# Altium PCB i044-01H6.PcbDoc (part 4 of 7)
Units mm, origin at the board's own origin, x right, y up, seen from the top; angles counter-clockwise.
Board outline 42 x 29.01 mm, 8 copper layers (Top Layer, Mid-Layer 1, Mid-Layer 2, Mid-Layer 3, Mid-Layer 4, Mid-Layer 5, Mid-Layer 6, Bottom Layer), stack 1.474 mm thick; 235 components, 197 nets, 1006 pads, 1183 vias.
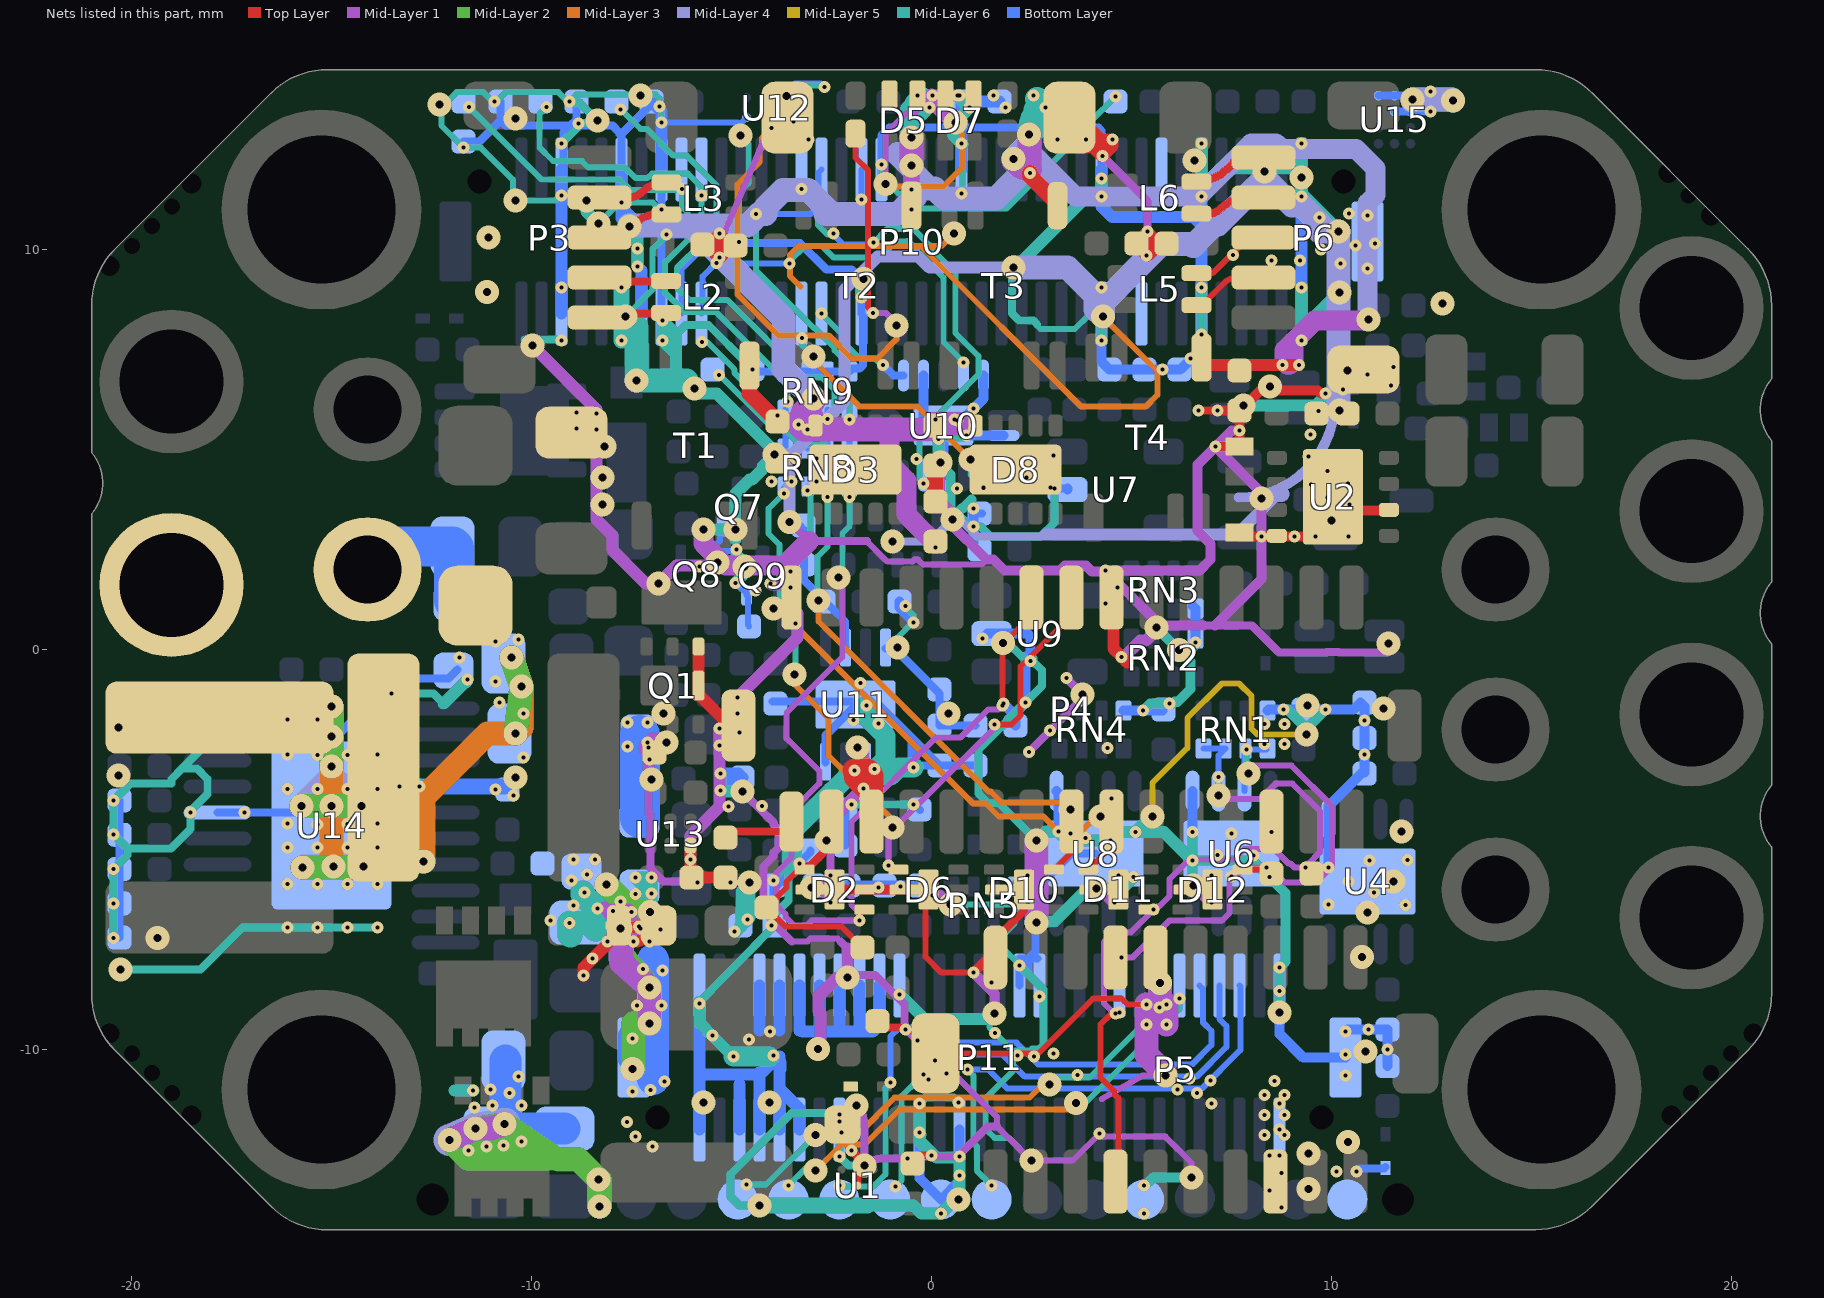
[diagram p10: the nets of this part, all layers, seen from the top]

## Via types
v1: diameter 0.3/0.3 (per signal layer), hole 0.1, Mid-Layer 6 to Bottom Layer, 515 vias
v2: diameter 0.3/0.3 (per signal layer), hole 0.1, Top Layer to Mid-Layer 1, 392 vias
v3: diameter 0.6, hole 0.2, Mid-Layer 1 to Mid-Layer 6, 276 vias

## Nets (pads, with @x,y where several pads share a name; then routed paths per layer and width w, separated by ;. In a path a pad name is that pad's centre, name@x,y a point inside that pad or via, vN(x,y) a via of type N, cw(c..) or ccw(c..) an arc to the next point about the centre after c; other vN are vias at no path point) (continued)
ENC_Z_IN/CLK_OUT_N: D12.6 P5.8 R11.2 RN1.1 RN1.3 U6.7 | length 14.7
  Top Layer w0.15: D12.6@7.775,-5.5 8.4,-5.5 R11.2@8.5,-5.6
  Top Layer w0.25: P5.8@4.6,-7.22 P5.8@4.6,-7.7 v2(4.75,-7.7)
  Mid-Layer 1 w0.15: v2(4.75,-7.7) 5.019,-7.7 5.944,-6.775 7.261,-6.775 7.45,-6.586 7.45,-5.814 7.814,-5.45 v2(8.375,-5.45) 8.452,-5.45 8.827,-5.825 9.505,-5.825 9.521,-5.81 9.627,-5.81 10.007,-5.429 10.007,-3.907 9,-2.9 7.975,-2.9 7.925,-2.95 v3(7.925,-3.094)
  Mid-Layer 6 w0.15: v3@7.875,-3.044 v1(7.875,-2.5)
  Bottom Layer w0.15: U6.7@7.825,-3.538 7.825,-2.5 v1(7.875,-2.5) RN1.1@8.375,-2.5
ENC_Z_IN/CLK_OUT_P: D11.4 P5.7 R11.1 RN1.5 RN1.7 U6.6 | length 19.6
  Top Layer w0.15: P5.7@4.575,-13.275 P5.7@4.6,-13.3 4.675,-13.225 4.675,-11.219 4.67,-11.213 4.58,-11.124 4.58,-11.052 4.232,-10.704 4.226,-10.699 4.225,-10.698 4.227,-10.332 4.225,-10.323 4.225,-9.369 4.494,-9.1 v2(4.6,-9.1)
  Mid-Layer 1 w0.15: v2(4.6,-9.1) 4.575,-9.1 4.309,-8.834 4.309,-7.316 4.55,-7.075 4.975,-7.075 v2(5.55,-6.5) 5.625,-6.425 5.686,-6.425 5.95,-6.161 5.95,-6.091 5.95,-5.736 6.436,-5.25 7.555,-5.25 7.823,-4.981 8.541,-4.981 8.559,-5 8.576,-5 8.926,-5.35 8.976,-5.35 9.076,-5.45 v2(9.35,-5.45) 9.4,-5.45 9.4,-5.35 9.424,-5.35 9.707,-5.067 9.707,-4.031 9.026,-3.35 8.604,-3.35 8.218,-3.736 7.411,-3.736 7.325,-3.65 v3(7.175,-3.65)
  Mid-Layer 6 w0.15: v3@7.175,-3.444 7.18,-3.439 v1(7.18,-3.18)
  Bottom Layer w0.15: RN1.7@6.8,-2.475 RN1.5@7.35,-2.475 7.175,-2.65 7.18,-2.655 v1(7.18,-3.18) 7.18,-3.532 U6.6@7.175,-3.538
ETH0_LED_LINK: D4.1 U12.B2 | length 18.4
  Top Layer w0.15: D4.1@-1.9,12.9 -1.9,12.3 -1.594,11.994 -1.594,8.554 v2(-1.46,8.42)
  Mid-Layer 1 w0.15: v2(-1.46,8.42) -1.145,8.42 v3@-0.825,8.1
  Mid-Layer 3 w0.15: v3(-3.627,13.837) -3.627,13.403 -4.235,12.795 -4.235,12.545 -4.3,12.48 -4.3,12.185 -4.85,11.635 -4.85,8.878 -3.827,7.855 -2.573,7.855 -1.993,7.275 -1.358,7.275 -0.877,7.756 v3(-0.877,8.1)
  Mid-Layer 6 w0.15: v3(-3.627,13.837) -3.627,13.948 -3.475,14.1 -2.71,14.1 v1(-2.67,14.06)
  Bottom Layer w0.15: U12.B2@-3.625,13.8 -3.625,13.93 -3.418,14.15 -2.76,14.15 v1(-2.67,14.06)
ETH0_RX_N: L3.1 P3.4 | length 1.8
  Top Layer w0.2: P3.4@-8.3,11.3 -7.591,11.3 ccw(c-7.591,11.821) -7.222,11.453 cw(c-6.625,10.855) L3.1@-6.625,11.7
ETH0_RX_P: L3.2 P3.3 | length 1.8
  Top Layer w0.2: P3.3@-8.235,10.3 ccw(c-8.235,11.41) -7.45,10.625 cw(c-6.786,9.961) -6.786,10.9 L3.2@-6.625,10.9
ETH0_TX_N: L2.1 P3.2 | length 1.7
  Top Layer w0.2: P3.2@-8.2,9.2 L2.1@-6.625,9.2
  Top Layer w0.25: P3.2@-8.3,9.3 P3.2@-8.2,9.2
ETH0_TX_P: L2.2 P3.1 | length 1.6
  Top Layer w0.2: P3.1@-8.2,8.4 L2.2@-6.625,8.4
ETH1_RX_N: L5.1 P6.4 | length 1.9
  Top Layer w0.15: L5.1@6.625,8.61 ccw(c6.625,8.936) 6.855,8.705 7.316,9.166 cw(c7.64,8.841) 7.64,9.3 P6.4@8.3,9.3
ETH1_RX_P: L5.2 P6.3 | length 2
  Top Layer w0.15: L5.2@6.625,9.41 7.029,9.41 7.919,10.3 P6.3@8.3,10.3
ETH1_TX_N: L6.1 P6.2 | length 1.8
  Top Layer w0.2: L6.1@6.625,10.9 6.923,10.9 ccw(c6.923,11.327) 7.225,11.025 cw(c7.889,10.361) 7.889,11.3 P6.2@8.3,11.3
ETH1_TX_P: L6.2 P6.1 | length 1.9
  Top Layer w0.2: L6.2@6.625,11.7 ccw(c6.625,12.786) 7.393,12.018 7.675,12.3 P6.1@8.3,12.3
ETH_MOD_LED_G: P10.66
ETH_MOD_LED_R: P10.63
FAULT_SIGNAL: P10.36 R27.1 | length 8.4
  Mid-Layer 6 w0.15: v1(-1.75,11.25) -1.709,11.25 -1.484,11.025 1.87,11.025 3.57,12.725 3.647,12.725 3.995,13.073 3.995,13.22 v1(4.6,13.825)
  Bottom Layer w0.15: v1(-1.75,11.25) P10.36@-1.75,12
GND_A: C24.1 C25.1 C32.1 C33.2 C34.1 L8.1 P11.1 P11.2 P11.5 P11.7 P11.8 P11.9 P11.10 P11.11 P11.12 P11.14 P11.16 P11.18 P11.20 U11.0 U11.4 | length 47
  Mid-Layer 6 w0.2: v1@-5.8,-8.812 -3.999,-6.975 v1@-3.962,-6.937 ; v1(-4,-6.9) -4,-6.698 -3.577,-6.275 -3.577,-5.359 ; v1(-3.95,-5.775) -3.95,-5.732 -3.577,-5.359 ; -3.5,-5.282 -3.577,-5.359
  Mid-Layer 6 w0.3: v1@-5.8,-8.812 v1(-5.8,-8.85) -5.784,-9.344 v1(-5.478,-9.65) v1(-4.953,-10.175)
  Mid-Layer 6 w0.5: v1(-4.953,-10.175) v1@-4.05,-10.175 ; -3.5,-5.282 -3.5,-4.56 -2.487,-3.547 -2.475,-3.547 -2.101,-3.173 -2.101,-3.15 -1.56,-3.15 ; v1(-1.625,-1.4) -1.625,-1.685 -1.15,-2.16 -1.15,-2.74 -1.56,-3.15 ; v1(-0.45,-2.95) -0.825,-2.95 -1.025,-3.15 -1.56,-3.15
  Bottom Layer w0.2: v1(-4,-6.9) -3.95,-6.85 v1(-3.95,-5.775) -3.95,-5.925 L8.1@-3.925,-5.9 -3.864,-5.9 -3.025,-5.061 C33.2@-3.025,-5.025 ; C34.1@-3.975,-1.3 -2,-1.3 U11.0@-1.9,-1.4 ; U11.4@-2.65,-2.825 U11.4@-2.65,-2.8 -2.65,-2.15 U11.0@-1.9,-1.4 ; v1@-0.498,-2.864 -0.498,-2.314 ; -0.4,-2.35 -0.4,-2.9 C25.1@0.2,-2.9 ; C24.1@1.1,-2.9 C25.1@0.2,-2.9 ; U11.0@-1.9,-1.4 v1(-1.625,-1.4) -1.3,-1.4 C25.1@0.2,-2.9
  Bottom Layer w0.3: P11.1@-5.8,-12 -5.8,-10.6 ; v1(-5.8,-8.85) -5.8,-10.6 ; P11.5@-4.8,-12 -4.8,-10.875 ; P11.7@-4.3,-12 -4.3,-10.625 ; -4.3,-10.575 -4.3,-10.625 ; -4.3,-9.525 P11.8@-4.3,-8.4 ; P11.9@-3.8,-12 -3.8,-10.3 ; -3.8,-10.975 -3.3,-11.475 P11.11@-3.3,-12 ; -3.8,-10.175 -3.8,-10.3 ; -3.8,-9.525 P11.10@-3.8,-8.4 ; -3.775,-10.486 -3.775,-10.325 -3.8,-10.3 ; -3.3,-9.525 P11.12@-3.3,-8.4 ; -3.225,-9.55 -1.775,-9.55 ; -2.8,-9.525 P11.14@-2.8,-8.4 ; -2.3,-9.525 P11.16@-2.3,-8.4 ; P11.18@-1.8,-8.4 -1.8,-9.525 -1.775,-9.55 ; P11.20@-1.3,-8.4 -1.3,-9.377 -1.473,-9.55 -1.775,-9.55 ; -5.8,-10.6 -5.775,-10.625 -4.3,-10.625 ; -4.3,-10.625 -3.95,-10.275 v1(-3.95,-10.15) -3.8,-10.3
  other v1: -4.563,-9.75 -4.032,-9.55 -3.3,-5.35 -1.325,-1.847 -1.954,-1.763 -1.773,-0.833
GND_D: C5.2 C6.1 C7.2 C8.1 C9.1 C10.2 C12.2 C13.1 C14.1 C15.1 C16.2 C17.2 C18.2 C19.2 C20.2 C21.2 C22.2 C23.1 C26.2 C27.2 C28.2 C30.2 C35.1 C36.2 C37.2 C39.2 C43.2 C53.1 C56.1 D2.2 D2.5 D3.EP D5.3 D5.4 D6.2 D7.3 D7.4 D8.EP D10.2 D11.2 D12.2 D13.2 D14.2 D25.1 D26.1 L4.2 L8.2 L12.2 P4.6 P4.13 P4.26 P4.29 P4.S2 P5.2 P5.10 P5.15 P5.S1 P6.S2 P10.5 P10.6 P10.11 P10.12 P10.15 P10.16 P10.35 P10.38 P10.46 P10.59 P10.60 P10.69 P10.70 P10.79 P10.80 P10.S2 P11.15 P11.22 P11.23 P11.27 P11.34 P11.36 P11.44 P11.59 P11.60 P11.S2 pad.10 pad.14 pad.18 Q1.4 Q1.7 Q7.2 Q8.2 Q9.2 R3.1 R4.1 R7.1 R8.1 R20.2 R21.2 R23.2 R24.2 R29.2 R41.1 R48.2 R54.1 RN1.2 RN2.2 RN3.8 RN4.7 RN5.2 RN9.1 RN9.3 RN9.5 RN9.7 U1.A2 U1.B2 U2.2 U2.8 U2.9 U4.0 U4.5 U6.0 U6.5 U7.2 U8.0 U8.5 U9.2 U10.1 U10.4 U10.7 U10.10 U10.13 U10.EP U12.D1 U13.3 U15.C2 U15.C3 U15.D1 U15.D2 U15.D3 | length 482.6
  Top Layer w0.15: D6.2@-0.075,-6 -0.15,-6.075 -0.15,-7.68 0.245,-8.075 v2(1.05,-8.075) ; P5.S1@0.1,-10.1 v2@2.15,-10.1 ; v2(2.15,-10.15) v2@2.15,-10.1 ; v2(5.375,-8.871) 4.901,-8.871 4.755,-8.725 4.037,-8.725 2.662,-10.1 v2@2.15,-10.1
  Top Layer w0.2: v2@-1.977,-12.548 -1.85,-12.675 U1.A2@-1.85,-13 U1.B2@-1.85,-13.4 ; R54.1@-1.35,-9.29 -1.196,-9.444 -0.733,-9.444 -0.677,-9.5 -0.5,-9.5 P5.S1@0.1,-10.1 ; R48.2@-0.45,-12.85 -0.25,-12.65 v2(0,-12.65) ; P5.2@1.6,-7.7 1.6,-7.24 2.312,-6.527 D10.2@2.312,-6 ; v2(6.675,5.975) v2(7.15,5.975)
  Top Layer w0.25: D2.2@-2.425,-6 D2.5@-1.675,-6 D6.2@-0.625,-6 D6.2@-0.075,-6 ; v2(1.05,-8.075) 1.35,-7.775 1.525,-7.775 P5.2@1.6,-7.7 ; v2(7.1,5.075) D14.2@7.7,5.075 v2(7.7,5.475) C12.2@7.7,5.975 ; v2(7.15,5.975) C12.2@7.7,5.975 ; D13.2@7.7,2.825 v2(8.25,2.825) v2(9.075,2.825) U2.9@9.425,2.825 ; v2(9.85,6.4) 9.736,6.4 9.661,6.475 8.214,6.475 7.714,5.975 C12.2@7.7,5.975 ; U2.9@10.35,3.475 U2.2@11.425,3.475
  Top Layer w0.3: U13.3@-6.025,-4.9 v2(-6.025,-5.25) -6.025,-5.675 R41.1@-6,-5.7 L4.2@-5.15,-5.7 ; Q1.4@-5.825,0.075 Q1.7@-5.825,-0.9 -5.825,-1.12 -5.045,-1.9 P4.S2@-4.825,-1.9 ; P4.13@4.5,1.3 4.55,1.3 4.55,0.024 v2(4.755,-0.181) 4.9,-0.326
  Top Layer w0.4: C8.1@0.1,3.7 C9.1@0.1,4.6
  Top Layer w0.6: v2(-1.925,-3.025) -1.598,-3.025 v2@-1.531,-3.092 ; P4.26@-1.5,-4.3 P4.26@-1.5,-3.581 ; -1.5,-3.156 P4.26@-1.5,-3.548 ; P4.26@-1.5,-3.581 -1.89,-3.19 -1.857,-3.19 P4.26@-1.5,-3.548 ; P4.26@-1.5,-3.581 P4.26@-1.5,-3.548
  Mid-Layer 1 w0.15: -3.493,-7.297 -3.103,-7.297 -3.03,-7.225 -2.35,-7.225 -2.278,-7.297 ; -1.615,2.712 -1.103,2.2 -0.478,2.2 -0.425,2.253 -0.342,2.253 -0.214,2.125 1.244,2.125 1.372,2.253 ; v3(-1.15,11.64) -1.15,12.892 -0.623,13.419 -0.406,13.419 v2(0.025,13.85) ; v3(2.5,-12.775) v3@2.49,-12.775 ; 4.26,-11.228 5.275,-10.65 v3(5.85,-10.647) ; v3(6.5,-13.2) 6.5,-12.828 5.847,-12.175 4.125,-12.175 3.525,-12.775 v3@2.49,-12.775 ; 0.599,-10.726 0.682,-10.726 1.643,-11.687 1.643,-11.928 v3@2.49,-12.775 ; 0.599,-10.726 0.6,-10.725
  Mid-Layer 1 w0.2: v3(-7,-3.25) -7.075,-3.325 -7.075,-4.088 -7.025,-4.138 -7.025,-5.475 -6.704,-5.796 -5.85,-5.796 -6.025,-5.621 v2(-6.025,-5.25) ; v3(-4.725,-3.55) v2@-4.299,-3.976 ; v2(-4.233,-3.911) v2@-4.299,-3.976 ; v3(-3.55,3.195) -3.067,2.712 -1.615,2.712 ; -3.493,-7.297 -3.975,-6.815 -3.986,-6.815 -3.986,-6.734 -4.2,-6.519 -4.2,-5.417 -3.95,-5.167 -3.95,-5.076 -3.827,-4.953 -3.827,-4.498 -3.95,-4.375 -3.95,-4.325 v2@-4.299,-3.976 ; -3.425,1.349 -3.375,1.299 -3.375,0.926 -3.35,0.901 ; v3(-2.625,-4.775) -2.7,-4.775 -2.725,-4.75 -2.525,-4.55 -2.525,-4.575 v2(-2.525,-5.65) ; -2.278,-7.297 -2.1,-7.475 ; v3(-2.1,-8.2) -2.03,-8.13 -1.414,-8.13 -0.679,-8.865 -0.679,-9.375 -0.669,-9.385 -0.669,-9.481 v2(-0.65,-9.5) -0.625,-9.5 v2(-0.35,-9.775) -0.35,-9.777 v2@0.113,-10.24 ; v3(-1.875,-11.4) cw(c-2.358,-11.883) -1.675,-11.883 v3(-1.675,-12.9) cw(c-1.253,-13.322) -1.253,-12.725 v2(-0.6,-12.725) cw(c-0.479,-12.846) -0.479,-12.675 v2@0,-12.675 ; v2(0,-12.65) v2@0,-12.675 ; v2(0.082,-10.27) v2@0.113,-10.24 ; v2(0.375,-10.6) v2@0.424,-10.551 ; 0.599,-10.726 v2@0.424,-10.551 ; v2@1.3,4 2.375,4 v2(2.375,4.3) ; 1.643,-11.928 1.402,-11.928 0.732,-12.598 ccw(c0.809,-12.675) v1(0.7,-12.675) v2@0,-12.675 ; v2(2.432,-2.559) 3.775,-1.215 v3(3.775,-1.125) 3.375,-0.725 v2(3.375,-0.711) ; v2(4.35,1.15) 4.714,1.514 v2@4.714,1.614 ; v3@5.549,0.55 v3(5.625,0.55) ; v3(6.55,-5.9) 6.575,-5.9 v3@6.675,-6 ; 6.8,0.6 7.09,0.6 8.009,0.6 8.684,-0.075 9.873,-0.075 9.886,-0.062 10.176,-0.062 10.189,-0.075 11.385,-0.075 v3@11.517,0.057 ; v2@7,-5.675 v2(7,-5.65) ; v2@0.113,-10.24 v2@0.424,-10.551
  Mid-Layer 1 w0.25: v3(-3,-5.95) -2.825,-5.95 v2(-2.525,-5.65) ; v3(0.225,4.675) 0.225,3.72 0.475,3.47 v3@0.475,3.25 ; v3@0.425,3.2 1.372,2.253 1.55,2.253 1.825,1.978 3.219,1.978 3.341,2.1 3.859,2.1 4.009,1.95 4.525,1.95 ; v2(1.05,-8.075) 1.575,-8.6 v3(1.575,-9.1) ; 6.8,0.6 5.728,0.6 4.714,1.614 4.525,1.803 4.525,1.95 ; 7.09,0.6 8.25,1.76 v2(8.25,2.825) v3(8.25,3.775) 8.25,3.925 v2(7.1,5.075) ; v2(7.7,5.475) 7.5,5.475 v2(7.1,5.075) ; 4.525,1.95 4.55,1.975 6.697,1.975 6.975,2.253 6.975,2.647 6.65,2.972 6.65,4.625 v2(7.1,5.075)
  Mid-Layer 1 w0.3: v3(-9.975,7.6) -8.375,6 v2(-8.375,5.9) v2(-8.375,5.5) v3@-8.375,5.275 ; v3(-8.175,5.075) v3@-8.375,5.275 ; v2(-7.075,-2.45) -7.075,-3.175 v3(-7,-3.25) ; v2(-6.025,-5.25) -6.025,-4.655 -5.3,-3.93 v2(-5.3,-2.4) ; v2(-5.3,-1.975) v2(-5.3,-2.4) ; v2@-5.25,-2.45 v2(-5.3,-2.4) ; v3@-5.15,2.1 -6.375,2.1 v3(-6.825,1.65) -7.137,1.65 -7.976,2.489 -7.976,2.849 -8.375,3.248 v3@-8.375,5.275 ; v2(-4.85,-1.2) -3.35,0.3 -3.35,0.901 ; v2(-4.025,1.65) -4,1.625 -3.679,1.625 ; -3.679,2.1 -3.679,1.754 -3.525,1.6 v2(-3.525,1.55) -3.525,1.449 -3.425,1.349 ; v3(-2.837,-9.988) -2.78,-9.93 -2.78,-9.679 -2.775,-9.674 -2.775,-9.086 -2.825,-9.036 -2.825,-8.664 -2.361,-8.2 v3(-2.1,-8.2) -2.1,-7.475 ; v3(-2.625,-4.775) -2.625,-4.675 -2.525,-4.575 -2.513,-4.563 -2.513,-4.26 -1.727,-3.475 v2(-1.7,-3.475) -1.7,-2.6 v3(-1.85,-2.45) ; v2(-2.525,-6.325) v2@-2.525,-6.2 ; v2@0,13.875 v2(0.025,13.85) ; v2(0.025,-6.15) 0.2,-6.15 v3@0.525,-6.475 ; v3@0.323,-1.6 v3(0.425,-1.6) ; v3@0.55,13.125 0.025,13.65 v2(0.025,13.85) ; v2(0.7,13.85) v2(0.025,13.85) ; v3@4.25,-6 v2(4.575,-6.325) ; v2(4.755,-0.181) 4.818,-0.181 5.224,0.225 5.353,0.225 v3@5.728,0.6 ; v2@-2.525,-6.2 -2.725,-6 v2@-2.525,-6.2 ; v3@6.675,-6 7,-5.675 v2(7,-6.325) v3@6.675,-6
  Mid-Layer 1 w0.5: v2(-7.075,-2.45) -6.949,-2.325 v3(-6.625,-2.325) ; v3(-5.7,3) -5.7,2.65 -5.15,2.1 -3.679,2.1 -3.067,2.712
  Mid-Layer 1 w0.6: v3(2.625,-6.825) v3(2.625,-4.775) ; v3(5.716,-8.336) 5.716,-8.871 ; v3(5.85,-10.647) 5.85,-10.601 5.375,-10.126 v2(5.375,-9.371) v2(5.375,-8.871) 5.716,-8.871 ; 5.716,-8.871 v2(5.875,-8.871) v2(5.875,-9.371) 5.716,-9.212 5.716,-8.871
  Mid-Layer 2 w0.4: v3(-5.925,6.525) v3@-5.925,6.6
  Mid-Layer 3 w0.15: -3.275,9.075 -3.54,9.34 -3.54,9.866 -3.315,10.091 -0.274,10.091 ; v3(-1.15,11.64) -1.085,11.575 0.292,11.575 0.775,12.058 0.775,12.878 0.6,13.053 v3(0.6,13.175) ; v3(0.56,10.4) 0.251,10.091 -0.274,10.091 ; v3(4.284,8.325) 5.65,6.959 5.65,6.372 5.353,6.075 3.742,6.075 -0.274,10.091
  Mid-Layer 4 w0.2: v3@-1.025,2.675 -1,2.7 v3(-0.975,2.7) -0.025,2.7 0.5,3.225 v3(0.525,3.25) 0.602,3.173 0.802,3.173 1.15,2.825 3,2.825 3.05,2.875 3.075,2.9
  Mid-Layer 4 w0.25: 7.675,3.8 ccw(c7.675,6.2) v3@10.075,6.2
  Mid-Layer 4 w0.3: v3(-3.55,3.195) -3.55,4.5 v3(-3.925,4.875) -3.501,4.875 -2.18,6.196 -2.18,8.995 -1.345,9.83 -0.331,9.83 -0.051,9.55 v3(2.049,9.55) ; v3@0.475,3.25 v3@0.5,3.225 ; 2.849,2.875 3.05,2.875 7.635,2.875 8.646,3.886
  Mid-Layer 4 w0.4: 8.646,3.886 8.749,3.886
  Mid-Layer 4 w0.6: v3(2.049,9.55) 3.401,9.55 4.1,8.851 4.1,8.509 v3(4.284,8.325) 4.284,8.681 5.744,10.14 6.49,10.14 6.538,10.092 7.076,10.63 7.16,10.63 8.32,11.79 9.01,11.1 9.261,11.1 9.7,10.661 9.7,10.45 v3(10.175,10.45) v3@10.175,6 ; v3@12.025,13.725 v3(12.025,13.75) 13.015,13.75 v3(13.04,13.725)
  Mid-Layer 5 w0.15: v3(5.525,-4.175) 5.525,-3.333 6.4,-2.458 6.4,-1.708 7.258,-0.85 7.692,-0.85 8,-1.158 8,-1.974 8.151,-2.125 v3(9.375,-2.125)
  Mid-Layer 6 w0.15: v3(-8.625,11.225) -8.747,11.225 -8.872,11.35 v1(-9.25,11.35) -9.291,11.35 -9.416,11.225 v3(-10.4,11.225) -10.465,11.29 -10.465,11.75 -11.265,12.55 v1(-11.7,12.55) -12.25,13.1 -12.25,13.575 v3(-12.3,13.625) -12.184,13.625 -11.871,13.938 -11.204,13.938 -10.966,13.7 v1(-10.925,13.7) -10.884,13.7 -10.646,13.938 -9.329,13.938 -9.091,13.7 v1(-9.05,13.7) -8.875,13.875 -6.9,13.875 -6.8,13.775 v1(-6.8,13.575) -6.75,13.525 v1(-6.75,13.175) ; v3(-8.325,10.65) -7.954,11.021 -7.944,11.021 -7.791,11.175 v1(-7.75,11.175) -6.966,11.175 -6.791,11 v1(-6.75,11) -6.75,10.546 -6.62,10.416 v1(-6.62,10.375) -6.97,10.025 -6.97,9.005 -7.625,8.35 v3@-7.75,8.35 ; v3@-6.775,-1.6 v3@-6.7,-1.525 ; v3(-5.35,2.175) -5.264,2.261 -5.029,2.261 -4.916,2.375 -4.916,2.459 v1@-4.887,2.488 ; v1@-4.887,2.437 v1@-4.853,2.437 ; v3@-4.887,2.75 v1@-4.887,2.488 ; v1(-4.817,10.194) -4.817,11.412 -4.575,11.654 -4.575,12.65 v3(-4.775,12.85) ; v3@-4.725,2.025 v3(-4.675,2.075) -4.736,2.136 -4.736,2.321 v1@-4.853,2.437 ; v1(-1.25,12.125) -1.25,11.825 -0.825,11.4 v1(0.75,11.4) 0.775,11.425 v1@0.775,12.625 ; v3(-0.85,0.05) -0.85,0.3 -0.47,0.68 v1(-0.45,0.68) -0.45,0.863 -0.65,1.063 v1(-0.65,1.09) ; v3(0.475,-6.375) v1@2.35,-6.375 ; v3@1.443,-9.232 1.443,-9.436 2.033,-10.025 ; v1(2.2,-7.9) 2.2,-7.88 1.782,-7.462 1.782,-7.138 2.069,-6.851 2.069,-6.656 v1@2.35,-6.375 ; 2.282,-0.2 2.287,-0.205 2.577,-0.205 2.577,-0.327 v1@2.577,-0.382 ; v1(2.425,-6.3) v1@2.35,-6.375 ; v3(2.5,-12.775) 1.932,-12.207 1.575,-12.207 1.355,-11.988 1.355,-11.214 2.033,-10.537 2.033,-10.025 ; 2.624,8.115 2.724,8.015 3.585,8.015 3.895,8.325 v3(4.284,8.325) ; 2.688,-10 2.713,-9.975 2.517,-9.975 2.467,-10.025 2.033,-10.025 ; v1@-4.887,2.488 v1(-4.875,2.5) -4.875,2.459 v1@-4.853,2.437
  Mid-Layer 6 w0.2: v3@-10.174,7.75 v1@-9.25,7.75 ; v1(-9.25,12.65) -8.844,13.056 -8.844,13.131 v1(-8.825,13.15) -8.806,13.169 -8.406,13.169 v3(-8.35,13.225) -8.806,13.681 -9.031,13.681 v1(-9.05,13.7) ; v1(-6.725,7.725) -6.58,7.87 -6.39,7.87 -6.15,8.11 -5.57,8.11 -4.61,7.15 -4.61,7.135 v1(-4.475,7) ; v3(-4.3,-13.9) -4.8,-13.9 -5.025,-13.675 -5.025,-13.115 -3.496,-11.586 v3@-2.061,-11.586 ; v3(-1.875,-11.4) v3@-2.061,-11.586 ; v1(-1.75,8.8) v1@-1.7,8.85 ; v3(-1.675,-12.9) -2.075,-12.9 v1(-2.3,-12.675) -2.3,-11.825 v3@-2.061,-11.586 ; v1(-0.3,-11.35) -0.15,-11.2 0.55,-11.2 v1(0.675,-11.325) ; v1(1.05,3.075) 1.222,3.075 1.472,2.825 2.728,2.825 3.075,3.172 v1(3.075,4.025) ; v3(1.79,0.169) 1.914,0.169 2.282,-0.2 ; v3(2.049,9.55) 2.01,9.511 2.01,8.4 2.185,8.225 2.55,8.225 2.642,8.133 ; v1(2.2,-7.9) 2.8,-8.5 2.8,-9.888 2.713,-9.975 ; v1@2.48,-0.23 2.577,-0.327 2.764,-0.514 2.764,-0.911 v1(2.35,-1.325) 1.175,-2.5 1.175,-3.598 1.409,-3.832 1.682,-3.832 v3(2.625,-4.775)
  Mid-Layer 6 w0.25: v1(-0.3,-12.075) v1@-0.25,-12.125 ; v3(0.225,4.675) 0.225,4.625 0.475,4.375 v3@0.475,3.25 ; 0.999,3.749 0.775,3.525 0.75,3.525 v3@0.475,3.25 ; v1(1.05,3.075) 0.95,3.075 0.775,3.25 v3(0.525,3.25) v3@0.475,3.25 ; v1(4.25,7.725) 4.25,8.291 v3(4.284,8.325) ; v1@5.313,-13.42 5.533,-13.2 v3(6.5,-13.2) ; v1@5.338,-1.475 5.463,-1.35 v1(5.95,-1.35) 6.03,-1.35 v1@6.08,-1.3 ; v3(5.625,0.55) v3(6.19,-0.015) v3@6.325,-0.15 ; 6.15,-1.31 6.475,-0.985 6.475,-0.3 v3@6.325,-0.15 ; v3@6.525,-5.975 v1(6.525,-5.275) ; v1(6.525,-4.562) v1(6.525,-5.275) ; v1(6.6,0.175) 6.6,0.125 v3@6.325,-0.15 ; v1(6.75,7.875) v1(6.75,9.05) ; v3(8.7,-9.075) v1(8.7,-8.54) v1(8.7,-7.95) 8.85,-7.8 8.85,-6.088 v1(8.45,-5.687) 8.037,-5.275 v1(6.525,-5.275) ; v1@8.9,-1.5 9.375,-1.975 v1(9.85,-1.5)
  Mid-Layer 6 w0.3: v3(-8.325,10.65) -8.625,10.95 v3(-8.625,11.225) -8.575,11.175 v1@-7.791,11.175 ; v3@-5.75,3 v3(-5.7,3) v3(-4.9,3) ; v3@-5.32,2.15 -4.711,1.959 -4.65,1.94 v1(-4.905,1.665) ; v1(-5.275,-3.1) v1(-5.275,-3.525) -5.25,-3.55 v3(-4.725,-3.55) ; v1@-4.912,-7.062 -4.756,-6.906 ; v3@-4.9,2.75 v3(-4.9,3) ; v3(-4.55,-5.825) v3@-4.55,-5.851 ; v1(-1.75,8.8) -1.75,9.216 v3(-1.7,9.266) ; -1.6,-13.9 -0.45,-13.9 -0.255,-14.095 v1(0.235,-14.095) 0.7,-13.63 v1(0.7,-12.675) 0.675,-12.7 0.126,-12.7 -0.3,-12.274 v1(-0.3,-12.075) v1(-0.3,-11.35) ; v1(-0.8,-8.625) -0.786,-8.625 -0.18,-9.232 1.443,-9.232 v3(1.575,-9.1) ; v1@0.16,5.28 0.15,5.28 v1(0.17,5.26) ; v3@0.225,4.625 0.17,4.68 v1(0.17,5.26) ; v3(0.56,10.4) v3@0.61,10.45 ; v1(0.58,5.749) v1@0.58,5.67 ; v1(0.65,13.85) v1(0.95,13.55) 0.55,13.15 0.55,12.85 v1(0.75,12.65) v1@0.775,12.625 ; v3@2.049,9.605 v3(2.049,9.55) 2.074,9.524 3.875,11.325 v1(4.25,11.325) ; v3(2.625,-6.825) 2.65,-6.8 3.069,-6.8 3.894,-5.975 v3(4.125,-5.975) 4.762,-5.975 v1(5.05,-5.687) ; v3(2.625,-4.775) 2.85,-4.55 v1(3.175,-4.55) 3.4,-4.775 v1(4.475,-4.775) 4.478,-4.775 4.69,-4.562 v1(5.1,-4.562) ; v1(4.25,11.775) v1(4.25,11.325) ; v3(5.525,-4.175) 5.487,-4.175 v1(5.1,-4.562) ; v1(6.525,-5.275) 5.812,-4.562 v1(5.1,-4.562) ; v1(6.75,12.65) 6.75,11.557 ; v3(7.8,6.1) 9.6,6.1 10.2,6.7 10.2,8.9 v3@10.175,8.925 ; v1(9.25,7.725) 9.25,8.159 ; v1(9.25,9.05) 9.25,8.159 ; v1(9.25,11.325) v1@9.25,11.402 ; v1(9.25,12.65) v3@9.25,12.025 ; -6.39,7.39 -6.39,6.99 -6.125,6.725 v3(-5.925,6.525) -5.8,6.4 -5.364,6.4 -3.925,4.961 v3(-3.925,4.875) -4.225,4.575 -4.225,4.514 -4.489,4.25 -4.55,4.25 -4.9,3.9 v3(-4.9,3) ; -6.39,7.39 -6.39,7.87 -6.39,7.89 v1(-6.725,8.225) v1(-6.725,7.725) -6.39,7.39 ; -4.756,-6.906 -4.756,-6.057 v3@-4.55,-5.851 ; -4.756,-6.906 v1(-4.6,-6.75) -4.55,-6.7 v3@-4.55,-5.851 ; v1(0.17,5.26) v1@0.26,5.35 ; v1@0.26,5.35 v1@0.58,5.67 ; v1@0.26,5.35 v1(0.875,5.35) 0.58,5.645 v1@0.58,5.67 ; v1(4.25,11.325) v1(6.75,11.325) 6.75,11.557 ; 6.75,11.557 7.218,12.025 v3@9.25,12.025 ; 9.25,8.159 9.409,8.159 v3@10.175,8.925 ; v1@9.25,11.402 v3@9.25,12.025 ; v1@9.25,11.402 10.175,10.477 v3(10.175,10.45) v3@10.175,8.925
  Mid-Layer 6 w0.4: v1(-7.75,7.725) -7.75,8.35 v1(-7.75,9.05) ; v3(-4.3,-13.9) -1.6,-13.9
  Mid-Layer 6 w0.6: v3(-7.65,8.325) -7.375,8.05 v3(-7.375,6.725) v3@-6.125,6.725 ; v3(12.025,13.75) v3@13,13.75
  Bottom Layer w0.15: v1@-6.75,13.125 v1(-6.75,13.175) -4.85,13.175 -4.8,13.125 U12.D1@-4.625,13.3 ; v1(-5.8,2.075) -5.64,2.075 -5.47,2.245 Q8.2@-5.47,2.37 ; Q8.2@-5.47,2.411 -5.47,2.543 -5.285,2.728 -5.285,3.025 Q7.2@-5.225,3.085 ; Q8.2@-5.415,2.471 -4.904,2.471 v1(-4.875,2.5) ; Q9.2@-4.625,1.36 -4.593,1.327 -4.593,0.613 R3.1@-4.56,0.58 ; C27.2@-0.3,-5.999 C27.2@-0.3,-5.9
  Bottom Layer w0.2: C43.2@-11.7,12.7 -11.3,12.7 -10.775,13.225 ; C39.2@-10.775,13.7 -10.775,13.225 ; P10.6@-9.25,12 -9.2,12.05 -9.2,12.924 -9.024,13.1 ; C37.2@-8.875,13.7 v1@-8.875,13.249 ; P10.12@-7.75,12 -7.75,12.889 ; R29.2@-7,13.7 -7,13.639 -7.75,12.889 ; P10.15@-6.75,8.4 -6.75,10.245 ; P10.16@-6.75,12 v1(-6.75,11) -6.75,10.425 -6.75,10.245 ; -5.06,10.375 v1(-6.62,10.375) -6.75,10.245 ; v1(-4.905,1.665) Q9.2@-4.63,1.45 ; v1@-4.854,10.169 -3.294,10.169 -2.625,9.5 -2,9.5 -1.8,9.3 -1.8,8.85 v1(-1.75,8.8) P10.35@-1.75,8.4 ; C36.2@-4.45,6.95 RN9.1@-3.65,6.95 RN9.3@-3.1,6.95 RN9.5@-2.6,6.95 RN9.7@-2.1,6.95 ; RN9.7@-2.05,6.95 -1.975,7.025 -1.8,7.025 -1.71,7.115 P10.35@-1.71,8.34 ; P10.38@-1.25,11.825 v1(-1.25,12.125) -1.25,12.85 -1.05,13.05 0.75,13.05 4.17,13.05 4.25,12.97 P10.60@4.25,12 ; C23.1@1.2,3.4 C23.1@1.264,3.4 ; RN5.2@2.1,-5.85 RN5.2@2.1,-5.925 v1@2.425,-6.25 ; P11.34@2.2,-8.4 v1(2.2,-7.9) 2.2,-7.725 2.425,-7.725 ; P11.36@2.65,-7.725 2.425,-7.725 ; P11.36@2.7,-8.4 2.425,-8.125 2.425,-7.725 ; v1(3.075,4.025) 3.375,4.025 U7.2@3.4,4 ; U8.0@4.1,-5.1 3.5,-5.1 2.425,-6.175 v1@2.425,-6.25 ; v1(6.6,0.175) RN2.2@6.6,0.275 ; v1(10.625,-13.05) 10.7,-12.975 11.315,-12.975 D25.1@11.35,-12.94 ; U15.D1@11.175,13.85 U15.D2@11.575,13.85 U15.D3@11.975,13.85 12.3,13.85 ; U15.C2@11.575,13.45 U15.C3@11.975,13.45 12.3,13.45 ; v1@12.425,13.575 12.3,13.45 ; 12.425,13.725 12.3,13.85 ; -10.775,13.225 -10.65,13.1 -9.024,13.1 ; -9.024,13.1 v1@-8.875,13.249 ; v1@-8.875,13.249 -8.726,13.1 -7.976,13.1 -7.8,12.924 -7.8,12.889 -7.75,12.889 ; 2.425,-7.725 2.6,-7.55 2.6,-6.475 v1(2.425,-6.3) v1@2.425,-6.25 ; 12.3,13.45 v1(12.475,13.45) 12.475,13.934 12.39,13.85 12.3,13.85
  Bottom Layer w0.25: L8.2@-2.925,-5.9 C30.2@-2.075,-5.9 C28.2@-1.175,-5.9 C27.2@-0.3,-5.9 ; U10.7@-1.2,5.35 U10.EP@0.05,5.35 ; C26.2@-0.8,1.2 -0.8,1.05 -0.45,0.7 v1(-0.45,0.68) ; P11.23@-0.3,-12 -0.3,-13.21 pad.10@0.235,-13.745 0.7,-13.28 P11.27@0.7,-12 ; U10.EP@-0.2,5.75 U10.10@-0.2,6.85 ; U10.4@0.3,4.35 U10.EP@0.3,5.6 ; U10.EP@0.55,5.35 v1(0.875,5.35) U10.1@1.8,5.35 ; U10.EP@0.625,5.6 1.3,6.275 U10.13@1.3,6.85 ; C22.2@1.05,2.65 v1(1.05,3.075) v1(1.05,3.525) ; v1(1.275,0.275) 1.4,0.4 2.398,0.4 2.48,0.318 v1(2.48,-0.28) 2.455,-0.28 2.35,-0.175 v1(2.35,-1.325) 2.1,-1.575 C21.2@2.1,-1.65 ; v1(1.8,-1.35) C21.2@2.1,-1.65 ; C21.2@2.1,-1.9 C21.2@2.1,-1.65 ; U8.5@3.125,-3.538 3.175,-3.588 v1(3.175,-4.55) ; U7.2@3.4,4 U7.2@3.4,4.025 ; P10.59@4.25,8.4 4.25,7.2 C20.2@4.45,7 R24.2@5.325,7 R23.2@6.2,7 6.216,7 6.763,7.547 ; RN4.7@4.8,-1.525 v1(5.288,-1.525) ; C19.2@5.775,-1.525 5.368,-1.525 5.543,-1.35 v1(5.95,-1.35) ; v1(6.525,-4.562) U6.5@6.525,-3.538 ; RN3.8@6.525,1.1 RN3.8@6.6,1.025 RN2.2@6.6,0.25 ; P10.69@6.75,8.4 6.75,7.56 6.763,7.547 ; P10.69@6.775,8.3 6.775,7.559 6.763,7.547 ; RN1.2@8.4,-1.525 8.425,-1.5 C17.2@9.3,-1.5 v1(9.85,-1.5) 10.55,-1.5 10.725,-1.325 10.825,-1.425 v1(10.825,-1.775) R21.2@10.825,-2.213 v1(10.825,-2.625) 10.825,-3.075 10.764,-3.075 9.925,-3.914 U4.5@9.925,-4.238 v1(9.925,-5.45) ; P11.60@8.7,-8.4 v1(8.7,-8.54) 8.7,-9.605 9.295,-10.2 P11.S2@10.35,-10.2 v1(10.35,-10.125) ; v1(10.35,-9.55) 10.4,-9.5 C16.2@11.4,-9.5 v1(11.4,-10) C15.1@11.4,-10.41
  Bottom Layer w0.3: v1(-9.25,9.05) P10.5@-9.25,8.4 P10.6@-9.25,12 ; v1@-7.75,11.17 P10.12@-7.75,12 ; R29.2@-7,13.7 -6.75,13.45 -6.75,13.125 P10.16@-6.75,12 ; v1(-6.75,11) -7.041,10.709 -7.409,10.709 -7.75,11.05 -7.75,10.787 -7.438,10.475 -6.8,10.475 -6.75,10.425 -5.074,10.425 v1@-4.836,10.187 ; v1(-5.275,-3.525) -4.95,-3.2 R7.1@-4.725,-3.2 -4.825,-3.1 v1(-5.275,-3.1) ; P10.46@0.75,12 0.75,13.05 C7.2@0.75,13.65 ; C7.2@0.8,13.7 C10.2@1.7,13.7 ; P10.60@4.25,12 4.25,11.081 4.521,10.81 6.56,10.81 ; P10.69@6.75,8.4 6.75,10.62 ; P10.70@6.75,12 6.75,11 ; 6.94,10.81 6.75,11 ; P10.79@9.25,8.4 P10.80@9.25,12 ; 6.56,10.81 6.75,10.62 ; 6.56,10.81 6.75,11 ; 6.75,10.62 6.75,11
  Bottom Layer w1: L12.2@-7.293,-4.204 C53.1@-7.293,-2.135
  other v1: 5.315,-14.095 5.315,-13.395 0.7,-13.15 10.125,-13.05 8.7,-12.65 8.7,-12 -2.3,-11.8 8.7,-11.35 10.35,-10.65 10.925,-9.5 4.7,-9.075 2.7,-8.675 -4.925,-7.05 9.925,-6.375 11.85,-6.388 11.065,-6.075 -1.325,-5.95 -0.775,-5.925 10.425,-5.8 7.5,-5.675 10.95,-5.275 11.9,-5.262 7.149,-5.136 8.05,-5.15 3.85,-4.713 7.5,-4.6 8.5,-4.562 -7.05,-2.75 -7.6,-2.425 -7.1,-2.325 -7.6,-1.825 -7.1,-1.825 8.8,-1.5 1.05,6.025 5.775,7 6.475,7.275 -9.25,7.725 4.25,9.05 10.9,9.525 10.225,9.65 8.5,9.725 9.213,9.725 7.535,9.866 9.732,10 10.6,10.1 11.093,10.15 9.7,10.8 10.9,10.85 10.442,10.9 1.85,13.55 1.55,13.85 12.475,13.959
  other v2: 8.75,-13.95 8.45,-13.517 8.75,-13.083 8.45,-12.65 -2,-12.525 8.325,-12.129 8.825,-12.129 4.2,-12.1 -2.25,-12.075 -2.3,-11.625 8.325,-11.629 8.825,-11.629 7,-11.35 8.325,-11.129 8.825,-11.129 6.637,-11.085 6.15,-11 6.975,-10.775 8.575,-10.786 6.45,-10.725 -0.206,-10.625 3.65,-10.629 2.558,-10.175 3.05,-10.1 1.583,-9.582 1.5,-8.325 2.4,-6.3 -5.85,-5.825 -5.025,-5.825 2.4,-5.65 4.669,-5.65 -5.075,-3.925 -1.425,-2.986 4.403,-2.463 8.325,-2.354 8.825,-2.354 -4.8,-2.075 2.963,-2.025 8.325,-1.854 8.825,-1.854 -4.85,-1.6 -3.4,0.65 -4.4,1.475 4.65,1.55 -3.525,1.95 4.35,1.975 9.6,2.825 10.425,2.825 10.45,3.625 9.9,3.8 0.64,4.03 1.3,4.04 2.975,4.05 9.491,4.13 10.41,4.15 -4,4.2 -3.5,4.2 -2.875,4.2 9.894,4.462 -3.4,4.775 -2.875,4.775 -0.37,4.76 9.425,4.825 3.05,4.85 9.475,5.375 -8.875,5.525 -8.875,5.925 9.675,5.964 10.287,6.5 11.49,6.6 10.9,6.875 11.55,7.07
  other v3: 0.675,-13.75 9.42,-13.48 9.425,-12.6 10.41,-12.31 -5.7,-11.325 -4.05,-11.325 10.85,-10.05 10.76,-7.69 10.9,-6.575 11.55,-5.8 11.75,-4.55 -6.7,-1.6 11.3,-1.475 9.4,-1.4 11.425,0.15 10,3.225 -8.225,3.625 -8.225,4.3 10.2,5.975 8.46,6.58 10.4,6.975 12.775,8.65 -11.11,8.938 10.2,8.925 -11.076,10.3 9.25,11.8 8.325,11.95 6.575,12.225 -10.4,13.275 -7.275,13.85
GND_DCDC: C4.1 C38.2 C40.2 C41.1 C45.1 C46.1 C48.2 C49.1 C50.1 C52.2 C54.1 C57.1 C58.1 C59.1 C60.1 L10.2 L12.1 NT1.2 P11.S1 R40.1 R43.2 R44.2 U14.6 U14.14 U14.21 | length 127.5
  Top Layer w0.3: v2(-8.7,-8.15) -8.7,-7.95 v2(-8.475,-7.725) -8.135,-7.385 ccw(c-8.221,-7.3) v2(-8.1,-7.3) ; v2(-7.45,-7.3) ccw(c-7.45,-6.757) -7.066,-7.141 C4.1@-6.825,-6.9 -7.134,-6.9 ccw(c-7.134,-8.266) R40.1@-7.857,-7.107 ; v2(-8.1,-7.3) cw(c-7.134,-8.266) R40.1@-7.857,-7.107 ; v2(-8.1,-7.3) ccw(c-8.1,-7.179) -8.015,-7.265 R40.1@-7.857,-7.107 ; v2(-8.1,-7.3) -7.735,-6.935 cw(c-7.65,-7.021) -7.65,-6.9 R40.1@-7.857,-7.107
  Mid-Layer 1 w0.3: -8.175,-6.448 -8.134,-6.5 ; v2(-8.1,-7.3) -7.766,-7.3 v2(-7.45,-7.3) -7.45,-7.053 v2(-7.319,-6.921) v2@-7.319,-6.871 ; v3@-7.915,-6.966 v3@-7.777,-6.966 ; v2@-7.85,-6.623 -7.775,-6.698 v3(-7.775,-6.966) ; -7.5,-6.74 v2@-7.5,-6.689 ; -8.134,-6.5 -8.057,-6.6 v3(-7.775,-6.966) ; -8.134,-6.5 -7.564,-6.5 v2(-7.5,-6.564) v2@-7.5,-6.689 ; v3@-7.777,-6.966 v3(-7.775,-6.966) ; v3@-7.777,-6.966 v3(-7.775,-6.966) ; v3(-7.775,-6.966) v3(-7.775,-6.966) ; v3(-7.775,-6.966) v3(-7.775,-6.966) ; v3(-7.775,-6.966) v2@-7.5,-6.689
  Mid-Layer 1 w0.6: v3(-12.05,-12.262) v3(-11.4,-11.975) -11.021,-11.971 v3(-10.67,-11.855) ; v3@-7.777,-6.966 -7.769,-7.213 -7.767,-7.29 -7.766,-7.3 -7.766,-7.31 -7.75,-7.828 v3(-7.057,-8.442) v3(-7.05,-9.35)
  Mid-Layer 2 w0.6: v3(-15.75,-3.908) v3(-15,-3.908) v3(-14.25,-3.908) ; v3(-15.725,-5.45) -14.225,-5.45 v3(-14.2,-5.425) -14.075,-5.3 v3(-12.701,-5.3) ; v3(-15,-2.925) v3(-15,-2.175) v3(-15,-1.425) ; v3(-10.5,-0.2) v3(-10.25,-0.925) v3(-10.4,-2.1) ; -10.177,-12.193 -10.215,-12.155 -10.232,-12.155 ; v3(-8.3,-13.925) v3@-8.3,-13.275 ; v3(-8.125,-5.875) -7.775,-6.225 ; v3(-7.47,-10.48) -7.455,-10.465 -7.455,-9.35 v3(-7.05,-9.35) v3(-7.057,-8.442) -7.725,-7.675 v3(-7.775,-6.966) ; v3@-11.809,-12.155 v3(-11.4,-11.975) v3(-10.67,-11.855) -10.232,-12.155 ; v3@-11.809,-12.155 v3(-12.05,-12.262) -11.587,-12.725 -9.4,-12.725 ; v3@-11.809,-12.155 -10.232,-12.155 ; -10.232,-12.155 -9.4,-12.725 ; -9.4,-12.725 -9.325,-12.75 -8.825,-12.75 v3(-8.325,-13.25) ; v3(-8.325,-13.25) cw(c-8.325,-13.275) v3@-8.3,-13.275 ; v3(-8.325,-13.25) v3@-8.3,-13.275 ; v3(-7.775,-6.966) -7.775,-6.225 ; v3(-7.775,-6.966) -7.399,-6.761 v3(-7.038,-6.564) -7.436,-6.564 -7.775,-6.225
  Mid-Layer 3 w0.6: v3(-15.75,-3.908) v3(-15,-3.908) ; v3(-15.725,-5.45) v3@-14.95,-5.45 ; v3(-15,-1.425) v3(-15,-2.175) v3(-15,-2.925) v3(-15,-3.908) ; v3@-14.225,-5.45 v3@-14.95,-5.45 ; v3(-12.701,-5.3) -12.701,-3.701 ; v3(-10.5,-0.2) v3(-10.25,-0.925) -10.25,-1.95 v3(-10.4,-2.1) -11.1,-2.1 -12.701,-3.701 ; v3(-15,-3.908) -15,-5.4 v3@-14.95,-5.45 ; v3(-15,-3.908) v3(-14.25,-3.908) -12.908,-3.908 -12.701,-3.701
  Mid-Layer 4 w0.6: v3@-15.7,-5.425 v3(-14.95,-5.425) v3(-14.2,-5.425) ; v3@-15.055,-3.213 v3(-15.75,-3.908) v3(-15,-3.908) ; v3(-15,-1.425) v3(-15,-2.175) v3(-15,-2.925) v3(-15,-3.908) ; v3@-14.945,-3.213 v3(-14.25,-3.908) v3(-15,-3.908) ; v3(-10.5,-0.2) v3(-10.25,-0.925) -10.25,-1.95 v3(-10.4,-2.1) ; v3(-8.325,-13.25) cw(c-8.325,-13.275) -8.3,-13.275 v3(-8.3,-13.925) ; v3(-8.125,-5.875) -7.775,-6.225 ; v3@-7.834,-6.966 v3(-7.775,-6.966) ; v3(-7.05,-9.35) -7.057,-9.343 v3(-7.057,-8.442) -7.775,-7.723 v3(-7.775,-6.966) ; v3(-7.038,-6.564) -7.373,-6.564 ; v3(-7.775,-6.966) -7.775,-6.225 ; v3(-7.775,-6.966) -7.373,-6.564 ; -7.775,-6.225 -7.436,-6.564 -7.373,-6.564
  Mid-Layer 4 w0.8: v3@-12.046,-12.26 v3(-11.4,-11.975) v3(-10.67,-11.855)
  Mid-Layer 5 w0.6: v3(-15.75,-3.908) v3(-15,-3.908) v3(-14.25,-3.908) ; v3(-15.725,-5.45) v3@-14.225,-5.45 ; v3(-10.5,-0.2) v3(-10.25,-0.925)
  Mid-Layer 6 w0.2: v1(-20.45,-7.204) v1(-20.45,-6.346) v1(-20.45,-5.489) -20.1,-5.139 -20.1,-4.975 ; v3(-20.275,-8) -18.275,-8 -17.225,-6.95 v1(-16.1,-6.95) v1(-15.35,-6.95) v1(-14.6,-6.95) v1@-13.95,-6.95 ; v1@-16.05,-1.7 v1(-16.1,-1.75) -17.511,-1.75 -18.736,-2.975 ; v1(-13.5,-1.1) -12.45,-1.1 -12.2,-1.35 ; -20.1,-4.975 -19.014,-4.975 -18.525,-4.486 v1(-18.525,-4.071) -18.525,-4.036 -18.1,-3.611 -18.1,-3.239 -18.364,-2.975 -18.736,-2.975 ; -20.1,-4.975 v1(-20.45,-4.625) v1(-20.45,-3.775) -20.025,-3.35 -19.006,-3.35 -19,-3.344 -19,-3.239 -18.736,-2.975
  Mid-Layer 6 w0.3: -12.2,-1.35 v1(-11.6,-0.75) ; -11.926,-11.025 v1(-11.467,-11.025) v1@-11.45,-11.025 ; v1@-7.31,-5.793 -7.2,-5.903 v1@-7.2,-6.9 ; v1(-7.275,-6.975) v1@-7.2,-6.9 ; v3@-7,-6.675 v1(-7,-6.1) ; v1@-7.2,-6.9 -7.038,-6.738 v3(-7.038,-6.564) v1@-7.038,-6.062 ; v1@-7.038,-6.062 v1@-7,-6.025 ; v1@-7.038,-6.062 v1(-7.4,-5.7) v1(-7,-5.7) ; v1@-7.038,-6.062 v1(-7,-6.1) ; v1@-7.038,-6.062 -7.038,-5.738 v1(-7,-5.7) ; v1(-7,-6.1) v1@-7,-6.025 ; v1@-7,-6.025 v1(-7,-5.7)
  Mid-Layer 6 w0.4: v1(-13.3,-3.425) v1(-12.8,-3.425)
  Mid-Layer 6 w0.6: -9.028,-7.15 -9.05,-7.128 v1(-9.05,-6.84) -8.56,-6.84 -8.4,-7 v1@-8.4,-6.4 ; v1@-8.725,-6.074 -8.725,-6.123 -8.5,-6.348 ; v3(-8.3,-13.925) v3@-8.3,-13.275 ; v3(-7.775,-6.966) -7.738,-7.634 -7.348,-8.096 v3(-7.057,-8.442) -7.053,-8.892 -7.053,-8.896 v3(-7.05,-9.35)
  Bottom Layer w0.2: C41.1@-20.3,-7.2 R44.2@-20.3,-3.771 ; U14.6@-17.85,-4.075 U14.21@-15.325,-4.075 ; -15,-2.3 -13.6,-0.9 ; C48.2@-13.2,-0.5 -13.6,-0.9 ; L10.2@-11.85,-0.5 -12.075,-0.725 -13.225,-0.725 -13.5,-1 v1(-13.5,-1.1) -13.6,-1 -13.6,-0.9
  Bottom Layer w0.3: C38.2@-8.919,-6.944 C38.2@-8.8,-6.825
  Bottom Layer w0.4: U14.21@-13.875,-3.425 v1(-13.3,-3.425) v1(-12.8,-3.425) U14.14@-12.15,-3.425 C49.1@-10.675,-3.425
  Bottom Layer w0.8: C60.1@-10.65,-10.275 -10.65,-10.675 -10.65,-11.675 C58.1@-10.95,-11.975 C59.1@-9.175,-11.975 ; P11.S1@-7.45,-10.2 -7.45,-9.7 -6.963,-9.213 ; -6.963,-10.73 -6.963,-9.213 ; -6.963,-7.759 -6.963,-9.213
  other v1: -11.575,-12.525 -11.125,-12.425 -10.7,-12.4 -6.975,-12.418 -10.25,-12.3 -7.4,-12.175 -7.61,-11.81 -11.425,-11.45 -10.975,-11.4 -10.25,-11.396 -10.547,-11.082 -7.47,-11.05 -11.025,-10.998 -7.025,-11.005 -6.675,-10.8 -10.325,-10.675 -7.475,-9.725 -7.368,-8.894 -6.755,-8.894 -6.725,-8.025 -7.218,-7.987 -13.85,-6.95 -9.525,-6.775 -8.35,-6.475 -8.95,-6.4 -7.775,-6.298 -7.406,-6.112 -8.675,-6.075 -16.1,-5.858 -15.35,-5.858 -14.6,-5.858 -13.85,-5.858 -9,-5.775 -8.615,-5.627 -8.95,-5.25 -8.419,-5.25 -16.1,-4.942 -15.35,-4.942 -14.6,-4.942 -13.85,-4.942 -15.35,-4.37 -16.1,-4.35 -14.6,-4.36 -13.85,-4.35 -17.175,-4.075 -10.45,-3.65 -16.1,-3.483 -15.35,-3.483 -14.6,-3.483 -13.85,-3.483 -10.9,-3.5 -10.2,-2.7 -15.35,-2.64 -14.6,-2.64 -16.1,-2.617 -13.85,-2.617 -15.35,-1.75 -10.2,-1.6 -10.8,-1.325 -10.9,-0.8 -11.8,-0.2 -10.9,0.2 -10.325,0.25
  other v2: -7.05,-7.3 -6.775,-7 -7.968,-6.532
  other v3: -19.35,-7.21 -10.4,-3.2 -20.325,-3.15 -20.325,-1.95
GND_P: C1.2 C2.2 C42.1 D1.1 H1.1 L10.1 P1.1 | length 4.1
  Top Layer w1.3: P1.1@-14.1,2 P1.1@-13.7,2
  Bottom Layer w1: P1.1@-14.1,2 -13.525,2.575 C42.1@-11.975,2.575 -11.938,2.538 L10.1@-11.938,1.23
GPI1: C43.1 P10.18 RN8.8 RN9.2 | length 14.5
  Mid-Layer 6 w0.15: v1(-11.558,13.563) -9.744,11.75 -7.787,11.75 -7.531,11.494 -6.271,11.494 v1(-6.243,11.522) -6.243,11.073 -6.1,10.93 -6.1,10.233 -6.665,9.668 -6.665,8.938 -6.162,8.435 -5.38,8.435 -3.6,6.655 v1(-3.6,6.2)
  Bottom Layer w0.15: RN8.8@-3.65,5.025 RN9.2@-3.65,6
GPI2: C37.1 P10.19 RN8.6 RN9.4 | length 11.1
  Mid-Layer 6 w0.15: v1(-7.775,13.5) -7.758,13.5 -7.275,13.018 -7.123,13.018 -6.455,12.35 -6.116,12.35 -5.375,11.609 -5.375,9.675 v1(-5.38,9.67) ; v1(-5.74,7.69) -5.61,7.69 -4.935,7.015 -4.935,7 -4.93,6.995 -4.93,6.925 -3.805,5.8 -3.4,5.8 v1(-3.1,5.5)
  Bottom Layer w0.15: P10.19@-5.75,8.4 -5.725,8.425 -5.725,9.325 v1(-5.38,9.67) ; RN8.6@-3.1,5.025 RN9.4@-3.1,6
GPI3: C39.1 P10.20 RN8.4 RN9.6 | length 15.4
  Mid-Layer 6 w0.15: v1(-9.625,13.563) -9.804,13.385 -9.804,12.555 -9.464,12.215 -8.74,12.215 -8.575,12.05 -7.662,12.05 -7.405,11.794 -7.095,11.794 -6.988,11.9 -6.197,11.9 ; v1@-2.6,5.825 v1(-2.6,5.761) -2.541,5.82 -2.602,5.881 -2.425,6.058 -2.425,6.492 -2.734,6.801 -3.164,6.801 -5.097,8.735 -6.037,8.735 -6.365,9.063 -6.365,9.543 -5.75,10.158 v1(-5.75,11.35) -5.75,11.559 -6.087,11.897 ; -6.197,11.9 -6.091,11.9 -6.087,11.897 ; -6.197,11.9 -6.193,11.897 -6.087,11.897
  Bottom Layer w0.15: RN8.4@-2.6,5.025 v1(-2.6,5.761) RN9.6@-2.6,6
GPI4: C36.1 P10.32 RN8.2 RN9.8 | length 13.9
  Mid-Layer 6 w0.15: v1(-5.31,6.86) -5.293,6.86 -3.933,5.5 -3.666,5.5 -3.291,5.125 -2.767,5.125 -2.617,5.275 -2.52,5.275 v1(-2.046,5.749) -2.046,6.354 -2.125,6.433 -2.125,7.183 -2.425,7.483 -2.425,7.547 -2.903,8.025 -2.926,8.025 -4.39,9.489 v1(-4.39,10.89)
  Bottom Layer w0.15: v1(-4.39,10.89) -3.03,10.89 -2.825,11.095 -2.825,11.925 P10.32@-2.75,12 ; RN8.2@-2.05,5.025 RN9.8@-2.05,6
GPO1: P10.29 U10.2 | length 6.5
  Mid-Layer 3 w0.15: v3(-2.95,7.33) -2.95,7.222 -1.808,6.08 -0.355,6.08 v3(0.975,4.75)
  Mid-Layer 6 w0.15: v1(-3.24,7.79) -3.24,7.62 v3(-2.95,7.33) ; v3(0.975,4.75) 0.975,4.375 v1(1.3,4.05)
GPO2: P10.30 U10.5 | length 11.5
  Mid-Layer 6 w0.15: v1(-3.25,11.522) -2.84,11.112 -2.84,10.617 -2.598,10.375 v1@-2.475,10.375 ; v1(-1.45,10.175) -1.115,10.51 -0.486,10.51 -0.484,10.508 -0.445,10.508 -0.05,10.113 -0.05,10.074 0.6,9.424 0.6,7.91 1.175,7.335 1.175,6.889 -0.3,5.414 -0.3,4.25 v1(-0.2,4.15)
  Bottom Layer w0.15: v1(-2.45,10.4) -2.462,10.388 -2.2,10.125 -1.525,10.125 v1@-1.45,10.2
GPO3: P10.31 U10.9 | length 2.8
  Mid-Layer 6 w0.15: v1(-2.75,8.4) -2.125,7.775 -2.125,7.608 -1.792,7.275 -1.41,7.275 -1.279,7.144 -1.226,7.144 v1@-1.21,7.16
  Bottom Layer w0.2: v1(-1.21,7.115) -0.945,6.85 U10.9@-0.7,6.85
GPO4: P10.17 U10.12 | length 11.3
  Mid-Layer 6 w0.15: v1(-3.55,9.65) -3.55,9.702 -3.167,10.085 -2.733,10.085 -2.448,9.8 -1.288,9.8 -0.88,10.208 -0.613,10.208 -0.61,10.21 -0.608,10.208 -0.57,10.208 -0.35,9.988 -0.35,9.95 0.3,9.3 0.3,7.69 0.8,7.19 v1(0.8,7.18)
  Bottom Layer w0.15: P10.17@-6.25,8.4 -6.25,9.509 -5.714,10.045 -5.225,10.045 -4.83,9.65 v1(-3.55,9.65)
IN1: D11.1 P4.14 RN8.7 | length 16.1
  Top Layer w0.15: D11.1@3.919,-5.5 4.5,-4.919 P4.14@4.5,-4.3
  Mid-Layer 1 w0.15: v3(4.225,-4.175) 4.5,-3.9 v2(4.5,-3.725)
  Mid-Layer 3 w0.15: v3(-3.95,1.025) -3.833,1.025 1.042,-3.85 1.362,-3.85 1.687,-4.175 2.803,-4.175 3.178,-4.55 3.728,-4.55 4.103,-4.175 v3(4.225,-4.175)
  Mid-Layer 6 w0.15: v3(-3.95,1.025) -3.8,1.175 -3.8,2.624 -4.075,2.899 -4.075,3.525 -3.7,3.9 v1(-3.69,3.9)
  Bottom Layer w0.15: v1(-3.69,3.9) -3.69,4.035 RN8.7@-3.65,4.075
IN2: D6.1 P4.15 RN8.5 | length 19
  Top Layer w0.15: v2(-1.075,-5.4) -0.975,-5.5 D6.1@-0.825,-5.5 ; v2(1.58,-1.87) 2.005,-1.87 2.225,-1.65 2.225,-0.425 3.5,0.85 P4.15@3.5,1.3
  Mid-Layer 1 w0.15: v2(-1.075,-5.4) -1.075,-4.55 v3(-0.975,-4.45) -0.918,-4.45 1.58,-1.952 v2(1.58,-1.87)
  Mid-Layer 3 w0.15: v3(-3.425,-0.625) -3.425,-0.867 -2.575,-1.717 -2.575,-2.65 -0.975,-4.25 v3(-0.975,-4.45)
  Mid-Layer 6 w0.15: v3(-3.425,-0.625) v3@-3.425,-0.575 ; v3@-3.35,-0.625 -3.4,-0.575 -3.4,2.275 -3.025,2.65 -3.025,3.875 v1@-3.125,3.975 ; v1@-3.1,3.96 v1(-3.1,3.98)
  Bottom Layer w0.15: v1(-3.1,3.98) RN8.5@-3.1,4.075
IN3: D10.6 P4.16 RN8.3 | length 13.7
  Top Layer w0.15: D10.6@3.062,-5.5 3.5,-5.063 P4.16@3.5,-4.3
  Mid-Layer 1 w0.15: v2(3.475,-4.6) v3(3.475,-4)
  Mid-Layer 3 w0.15: v3(-2.825,1.225) -2.825,0.708 1.433,-3.55 1.487,-3.55 1.762,-3.825 3.3,-3.825 v3(3.475,-4)
  Mid-Layer 6 w0.15: v3(-2.825,1.225) -2.85,1.25 -2.85,2.325 -2.6,2.575 v1(-2.6,3.817)
  Bottom Layer w0.15: v1(-2.6,3.817) RN8.3@-2.6,4.075
IN4: D2.4 P4.17 RN8.1 | length 25.6
  Top Layer w0.15: v2(-1.8,-6.775) -1.8,-6.625 D2.4@-1.675,-6.5 ; v2(1.775,-1.4) 1.775,0.125 2.725,1.075 P4.17@2.5,1.3
  Mid-Layer 1 w0.15: v3@-2.45,1.85 -2.4,1.8 v3(-2.325,1.8) -2.225,1.7 -2.225,-0.183 -3.625,-1.583 -3.625,-2.217 -2.8,-3.042 -2.8,-3.341 -3.502,-4.043 -3.502,-5.202 -3.875,-5.575 -3.875,-6.385 -3.65,-6.61 -3.65,-6.68 -3.43,-6.9 -3.12,-6.9 -2.995,-6.775 v2(-1.8,-6.775) -1.8,-6.574 -2,-6.374 -2,-4.308 0.108,-2.2 0.72,-2.2 1.425,-1.495 1.68,-1.495 v2(1.775,-1.4)
  Mid-Layer 6 w0.15: v3(-2.325,1.8) -2.225,1.9 -2.225,2.905 -2.05,3.08 v1(-2.05,3.817)
  Bottom Layer w0.15: v1(-2.05,3.817) RN8.1@-2.05,4.075
MAGNETICS_CT: C5.1 C7.1 C8.2 C9.2 C10.1 C12.1 D3.5 D8.5 P10.13 T1.6 T2.6 T3.6 T4.6 | length 62.8
  Top Layer w0.3: T4.6@6.75,7.3 6.75,7.21 6.85,7.11 v2@9.175,7.11
  Top Layer w0.4: T1.6@-4.55,7.1 -4.55,6.4 C5.1@-3.85,5.7 ; v2(2.457,11.918) 2.457,11.843 T3.6@3.2,11.1
  Mid-Layer 1 w0.4: v2(-0.5,11) v2(-0.5,11.5) v3(-0.5,12.1)
  Mid-Layer 1 w0.5: -1.05,5.5 -1.05,4.65 -0.63,4.23 -0.63,3.38 v2@0.1,2.65 ; v2@8.827,7.202 8.827,7.477 9.05,7.7 ; v2@8.902,7.127 8.952,7.127 9.05,7.225 9.05,7.7 ; v3(10.925,8.25) 10.906,8.231 10.496,8.231 10.49,8.225 9.575,8.225 9.05,7.7
  Mid-Layer 1 w0.6: v3@-2.95,6.199 -3.214,5.935 -3.214,5.835 ; v3(-0.5,12.1) v3(-0.5,12.8) ; v2@0.65,5.649 0.1,5.649 -0.049,5.5 -1.05,5.5 -3.2,5.5 v2(-3.325,5.625) ; v3@2.05,12.225 2.145,12.13 ccw(c2.457,12.442) 2.457,12.001 2.451,12.007 v3@2.451,12.882 ; v2(-3.325,5.625) -3.325,5.724 -3.214,5.835 ; v2(-3.325,5.625) v2@-3.214,5.625 ; v2@-3.214,5.625 -3.214,5.835 ; v2@-3.214,5.625 -3.004,5.835 -3.214,5.835
  Mid-Layer 4 w0.5: v3@2.451,12.661 2.451,12.474 3.595,11.33 6.67,11.33 7.99,12.65 8.615,12.65 8.748,12.517 10.616,12.517 11.101,12.032 11.101,11.368 10.9,11.167 v3@10.9,8.25
  Mid-Layer 4 w0.6: v3@-7.55,10.606 -6.02,10.606 ; v3@-2.95,6.3 -3.23,6.58 -3.261,6.58 -3.7,7.019 -3.7,8.286 -6.02,10.606 ; -0.839,12.39 -0.5,12.051 v3(-0.5,12.1) v3(-0.5,12.8) ; v3(2.05,12.261) v3@2.087,12.298 ; v3@2.451,12.661 v3@2.087,12.298 ; -6.02,10.606 -4.595,10.606 -4.311,10.89 -4.15,10.89 -4.15,11.051 -3.711,11.49 -3.089,11.49 -2.65,11.051 -2.65,10.89 -0.839,10.89 -0.4,11.329 -0.4,11.864 -0.061,11.525 0.075,11.525 0.325,11.275 1.611,11.275 2.361,12.025 v3@2.087,12.298
  Mid-Layer 6 w0.3: v3@-7.575,10.55 v3@-7.562,10.563 ; v3(-7.55,10.575) v3@-7.562,10.563 ; v1(-7.35,9.575) v1(-7.35,10.025) -7.35,10.35 v3@-7.562,10.563 ; -0.47,13.14 -0.05,13.56 v1@-0.25,13.76
  Mid-Layer 6 w0.6: v3(-0.5,12.1) v3(-0.5,12.8) -0.5,13.462 -0.373,13.589 -0.373,13.637 v1@-0.25,13.76 ; v3(2.05,12.261) v3@2.125,12.336 ; v3@2.069,12.275 ccw(c1.33,13.014) v3@2.125,12.336 ; v1@2.64,13.76 v1@2.76,13.64 ; v1@2.769,13.649 ccw(c3.536,12.882) v1@2.76,13.64 ; v3@2.125,12.336 2.451,12.661 v3@2.451,12.882 ; v3@2.451,12.882 cw(c3.536,12.882) 2.605,13.44 ; v3@2.451,12.882 2.605,13.036 2.605,13.44 ; 2.605,13.44 cw(c3.536,12.882) v1@2.76,13.64 ; 2.605,13.44 2.605,13.486 v1@2.76,13.64
  Bottom Layer w0.3: v1(-7.35,10.025) v1(-7.35,9.575) -7.25,9.475 P10.13@-7.25,8.4
  other v1: -0.05,13.55 2.85,13.55 -0.35,13.85 2.55,13.85
  other v2: 0.1,2.55 0.65,5.725 0.1,5.75 -3.85,5.85 8.772,7.111 9.19,7.111
  other v3: -2.95,6.275 2.435,12.875
MOCO_JTAG_TCK: P11.56 pad.11 | length 12.2
  Mid-Layer 6 w0.15: v1(0.9,-10.5) 1.05,-10.65 1.05,-12.326 1.135,-12.411 1.135,-13.025 v1(1.505,-13.395)
  Bottom Layer w0.15: v1(0.9,-10.5) 1.425,-10.5 1.9,-10.975 6.754,-10.975 7.725,-10.004 7.725,-8.425 P11.56@7.7,-8.4
MOCO_JTAG_TDI: P11.48 pad.6 | length 12.1
  Mid-Layer 3 w0.15: v3@-2.9,-12.074 -1.799,-12.074 -0.925,-11.2 2.45,-11.2 v3@2.775,-10.875
  Mid-Layer 6 w0.15: v1(-4.625,-13.375) -4.139,-13.375 v3(-2.9,-12.136) ; v3@2.775,-10.875 2.95,-10.7 3.95,-10.7 v1(5.7,-8.95)
  other v3: 2.95,-10.875
MOCO_JTAG_TDO: P11.52 pad.8@-2.305,-13.745 | length 15.1
  Mid-Layer 6 w0.15: v1(-2.305,-13.395) -2.275,-13.425 -1.458,-13.425 -1.15,-13.117 -1.15,-10.95 v1(-1.025,-10.825)
  Bottom Layer w0.15: v1(-1.025,-10.825) -1.025,-9.67 -0.805,-9.45 -0.225,-9.45 0.15,-9.825 2.125,-9.825 2.675,-10.375 6.505,-10.375 7,-9.88 7,-9.534 6.791,-9.325 6.791,-8.491 P11.52@6.7,-8.4
MOCO_JTAG_TMS: P11.50 pad.7 | length 12
  Mid-Layer 3 w0.15: v3(-2.9,-13.025) -2.25,-12.375 -1.676,-12.375 -0.801,-11.5 3.448,-11.5 v3(3.618,-11.33)
  Mid-Layer 6 w0.15: v1(-3.575,-13.395) -3.155,-12.975 v3@-2.825,-12.975 ; v3(3.618,-11.33) 3.85,-11.33 6.2,-8.98 v1(6.2,-8.725)
MOCO_JTAG_TRST: P11.54 pad.9 | length 13
  Mid-Layer 6 w0.15: v1(-0.9,-13.425) -0.75,-13.275 -0.75,-11.164 -0.336,-10.75 v1(-0.075,-10.75)
  Bottom Layer w0.15: v1(-0.075,-10.75) 0.55,-10.125 1.783,-10.125 2.333,-10.675 6.63,-10.675 7.375,-9.93 7.375,-9.414 7.2,-9.239 P11.54@7.2,-8.4
MOTOR_TEMP_IN: D2.1 P4.28 R5.1 R6.2 | length 5.8
  Top Layer w0.15: D2.1@-3.175,-5.5 -3.321,-5.5 -3.625,-5.804 -3.625,-5.95 -3.65,-5.975 R5.1@-4.125,-6.45 -3.657,-6.918 -2.257,-6.918 R6.2@-1.725,-7.45
  Top Layer w0.2: D2.1@-3.175,-5.5 -3.125,-5.5 -2.5,-4.875 P4.28@-2.5,-4.3
MOTOR_TEMP_RET: L4.1 P4.30 | length 1.9
  Top Layer w0.2: L4.1@-5.025,-4.675 -5.025,-4.55 -3.5,-4.55 P4.30@-3.5,-4.3
NetC3_2: C3.2 R9.1 R10.2 | length 5.8
  Top Layer w0.2: R9.1@-5.725,10.125 ccw(c-5.665,10.185) R9.1@-5.665,10.1
  Top Layer w0.3: R9.1@-5.725,10.125 R9.1@-5.625,10.125 ; R9.1@-5.7,10.1 -5.665,10.1 R9.1@-5.6,10.1 ; R10.2@-4.986,10.175 -4.986,10.114 R10.2@-5,10.1 ; R10.2@-4.9,10.1 R10.2@-5,10.1 ; R9.1@-5.625,10.125 R9.1@-5.6,10.1 ; R9.1@-5.625,10.125 -5.575,10.125 -5.303,10.397 R10.2@-5.006,10.1 ; R9.1@-5.6,10.1 v2(-5.3,9.8) R10.2@-5,10.1 ; R9.1@-5.6,10.1 R10.2@-5.006,10.1 ; R10.2@-5.006,10.1 R10.2@-5,10.1
  Mid-Layer 1 w0.15: v2@-5.225,10.325 -5.209,10.361 -4.225,12.65 -4.2,12.725 v2(-4,13.04)
  other v2: -5.3,10.4 -3.07,12.75 -3.45,13.2
NetC11_2: C11.2 R14.2 R15.1 | length 11.8
  Top Layer w0.2: R15.1@4.975,10.175 ccw(c5.035,10.235) R15.1@5.035,10.15 ; R15.1@5.125,10.125 cw(c5.185,10.065) 5.185,10.15 5.694,10.15 5.7,10.15 R14.2@5.8,10.15
  Top Layer w0.3: C11.2@3.687,12.55 4.275,12.55 ; v2(3.862,12.75) C11.2@3.862,12.732 ; 4.278,12.725 3.703,13.3 C11.2@3.45,13.3 C11.2@3.45,13.237 ; R15.1@4.975,10.175 R15.1@5.075,10.175 ; R15.1@5,10.15 5.035,10.15 R15.1@5.1,10.15 ; R15.1@5.185,10.15 R15.1@5.1,10.15 ; R14.2@5.694,10.15 5.397,10.447 5.125,10.175 R15.1@5.075,10.175 ; R14.2@5.714,10.225 5.714,10.164 5.7,10.15 5.4,9.85 v2(5.375,9.85) 5.375,9.875 5.125,10.125 R15.1@5.1,10.15 ; C11.2@3.45,13.237 3.937,12.75 v2(4.525,12.75) 4.525,12.591 ; C11.2@3.45,13.237 3.45,13.145 C11.2@3.862,12.732 ; C11.2@3.862,12.732 C11.2@3.937,12.658 ; C11.2@3.937,12.658 4.253,12.341 v2(4.275,12.341) 4.525,12.591 ; C11.2@3.937,12.658 4.092,12.658 4.159,12.591 4.525,12.591 ; R15.1@5.075,10.175 R15.1@5.1,10.15
  Mid-Layer 1 w0.2: v2(3.862,12.75) 5.4,11.212 v2(5.4,10.45) v2@5.4,9.875
  other v2: 3.15,12.75
NetC24_2: C24.2 C25.2 L7.1 U11.8 | length 3.5
  Bottom Layer w0.2: U11.8@-1.15,0.025 -0.925,0.025 0.2,-1.1 C25.2@0.2,-1.9 C24.2@1.1,-1.9
NetC29_1: C29.1 R30.2 R32.1 U11.2 | length 3.8
  Mid-Layer 6 w0.2: v1(-2,-3.875) v1(-0.45,-3.875)
  Bottom Layer w0.2: R32.1@-2.15,-4.9 C29.1@-2.15,-4 -2.15,-3.975 -1.65,-3.475 U11.2@-1.65,-2.825 ; R30.2@-0.3,-4 R30.2@-0.29,-4.01
NetC31_1: C31.1 R33.1 R34.2 U11.6 | length 3.6
  Bottom Layer w0.17: -2.374,0.922 -2.15,0.698 U11.6@-2.15,0.05
  Bottom Layer w0.2: R34.2@-3.3,3.1 -3.187,2.987 -3.187,1.735 -2.374,0.922 ; U11.6@-2.15,0.025 U11.6@-2.15,0.05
